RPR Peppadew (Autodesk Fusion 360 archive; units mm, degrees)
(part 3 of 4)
sketch "Sketch151" plane through (3.8207, 0, 14.3278) normal (0.2577, 0, 0.9662) x axis (0.9662, 0, -0.2577)
  line L1 (61.9037, -4.2015) -> (61.9037, -2.2015)
  line L2 (59.6949, -4.2015) -> (61.9037, -4.2015)
  line L3 (59.6949, -8.2015) -> (59.6949, -4.2015)
  line L4 (65.3871, -8.2015) -> (59.6949, -8.2015)
  line L5 (65.3871, -32.0015) -> (65.3871, -8.2015)
  line L6 (59.6949, -32.0015) -> (65.3871, -32.0015)
  line L7 (59.6949, -38.0015) -> (59.6949, -32.0015)
  line L8 (65.3871, -38.0015) -> (59.6949, -38.0015)
  line L9 (65.3871, -65.6015) -> (65.3871, -38.0015)
  line L10 (59.6949, -65.6015) -> (65.3871, -65.6015)
  line L11 (59.6949, -71.6015) -> (59.6949, -65.6015)
  line L12 (65.3871, -71.6015) -> (59.6949, -71.6015)
  line L13 (65.3871, -95.4015) -> (65.3871, -71.6015)
  line L14 (59.6949, -95.4015) -> (65.3871, -95.4015)
  line L15 (59.6949, -99.4015) -> (59.6949, -95.4015)
  line L16 (21.6089, -99.4015) -> (59.6949, -99.4015)
  line L17 (21.6089, -95.4015) -> (21.6089, -99.4015)
  line L18 (15.3992, -95.4015) -> (21.6089, -95.4015)
  line L19 (15.3992, -90.8015) -> (15.3992, -95.4015)
  line L20 (2.3072, -90.8015) -> (15.3992, -90.8015)
  line L21 (2.3072, -101.4015) -> (2.3072, -90.8015)
  line L22 (67.4569, -101.4015) -> (2.3072, -101.4015)
  line L23 (67.4569, -2.2015) -> (67.4569, -101.4015)
  line L24 (61.9037, -2.2015) -> (67.4569, -2.2015)
  line L25 (-10.2157, -101.4015) -> (-18.133, -101.4015)
  line L26 (-10.2157, -90.8015) -> (-10.2157, -101.4015)
  line L27 (-13.2688, -90.8015) -> (-10.2157, -90.8015)
  line L28 (-18.133, -90.8015) -> (-13.2688, -90.8015)
  line L29 (-18.133, -101.4015) -> (-18.133, -90.8015)
  line L30 (107.867, -38.0015) -> (10.7417, -38.0015)
  line L31 (107.867, -2.2015) -> (107.867, -38.0015)
  line L32 (-18.133, -2.2015) -> (107.867, -2.2015)
  line L33 (-18.133, -33.0015) -> (-18.133, -2.2015)
  line L34 (10.7417, -33.0015) -> (-18.133, -33.0015)
  line L35 (10.7417, -38.0015) -> (10.7417, -33.0015)
  line L36 (107.867, -133.2165) -> (107.867, -38.0015)
  line L37 (107.867, -101.4015) -> (-18.133, -101.4015)
  line L38 (107.867, -90.8015) -> (107.867, -101.4015)
  line L39 (-18.133, -90.8015) -> (107.867, -90.8015)
  line L40 (-18.133, -101.4015) -> (-18.133, -90.8015)
  line L41 (15.3992, -65.6015) -> (107.867, -65.6015)
  line L42 (15.3992, -90.8015) -> (15.3992, -65.6015)
  line L43 (107.867, -90.8015) -> (15.3992, -90.8015)
  line L44 (107.867, -65.6015) -> (107.867, -90.8015)
  line L45 (21.6089, -73.6015) -> (21.6089, -83.6015)
  line L46 (15.3992, -73.6015) -> (21.6089, -73.6015)
  circle C1 centre (64.536, -35.0015) radius 1.25
  circle C2 centre (64.4569, -5.2015) radius 1.25
  circle C3 centre (13.7417, -35.0015) radius 1.6
  circle C4 centre (-14.633, -29.5015) radius 1.6
  circle C5 centre (64.536, -35.0015) radius 1.6
  circle C6 centre (-14.633, -5.7015) radius 1.6
  circle C7 centre (64.4569, -5.2015) radius 1.6
  circle C8 centre (64.4569, -68.6015) radius 3
  circle C9 centre (64.4569, -68.6015) radius 1.25
  circle C10 centre (64.4569, -68.6015) radius 1.6
  circle C11 centre (64.4569, -98.4015) radius 3
  circle C12 centre (64.4569, -98.4015) radius 1.6
  circle C13 centre (64.4569, -98.4015) radius 1.25
  circle C14 centre (-15.133, -96.1015) radius 3
  circle C15 centre (-15.133, -96.1015) radius 1.6
  circle C16 centre (-15.133, -96.1015) radius 1.25
  circle C17 centre (18.6089, -76.6015) radius 1.6
  circle C18 centre (18.6089, -76.6015) radius 3
  circle C19 centre (18.6089, -76.6015) radius 1.25
  point P39 (107.867, -38.0015)
  point P44 (107.867, -38.0015)
  point P48 (107.867, -90.8015)
  point P28 (-18.133, -101.4015)
  point P46 (-18.133, -101.4015)
  point P23 (15.3992, -90.8015)
  point P52 (15.3992, -90.8015)
  point P50 (107.867, -65.6015)
  point P13 (65.3871, -65.6015)
  point P61 (-15.133, -96.1015)
  coincident P39 P44
  perpendicular L30 L36
  horizontal L37
  vertical L38
  horizontal L39
  vertical L40
  coincident L36 P48
  coincident P28 P46
  horizontal L41
  vertical L42
  horizontal L43
  vertical L44
  coincident P23 P52
  coincident L36 P50
  coincident P13 L41
  concentric C8 C9
  concentric C9 C10
  concentric C11 C12
  concentric C11 C13
  concentric C14 C15
  concentric C14 C16
  concentric C17 C18
  concentric C17 C19
  tangent C18 L45
  tangent C18 L46
  tangent L40 C14
  tangent L37 C11
  tangent L23 C11
  tangent L23 C8
  tangent L41 C8
  dimension "d856" diameter C8 = 6
  dimension "d857" diameter C9 = 2.5
  dimension "d858" diameter C10 = 3.2
  dimension "d859" diameter C11 = 6
  dimension "d860" diameter C12 = 3.2
  dimension "d861" diameter C13 = 2.5
  dimension "d862" diameter C14 = 6
  dimension "d863" diameter C15 = 3.2
  dimension "d864" diameter C16 = 2.5
  dimension "d865" diameter C17 = 3.2
  dimension "d866" diameter C18 = 6
  dimension "d867" diameter C19 = 2.5
  dimension "d868" distance L37 P61 = 5.3
extrude "Extrude16" cut sketch "Sketch151" profile of C9 C13 C16 C19 against normal blind 10
extrude "Extrude17" new body sketch "Sketch151" profile of L10 L11 L12 L13 L14 L15 L16 L17 L18 L19 L20 L21 L22 L23 L25 L26 L27 L28 L29 L36 L37 L38 L39 L40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 along normal blind 1
extrude "Extrude182" add of existing geometry blind 8.971
extrude "Extrude183" add of existing geometry blind 24
sketch "Sketch152" plane through (0, -33.0015, 0) normal (0, 1, 0) x axis (-1, 0, 0)
  line L1 (-9, -11) -> (-13.1998, -11)
  line L2 (-9, -2.3714) -> (-9, -11)
  line L3 (-6.9285, -2.3714) -> (-9, -2.3714)
  line L4 (-5.6202, -2.3714) -> (-6.9285, -2.3714)
  line L5 (3, -5.1) -> (-3, -5.1)
  line L6 (6.9285, -2.3714) -> (5.6202, -2.3714)
  line L7 (9, -2.3714) -> (6.9285, -2.3714)
  line L8 (9, 17.7467) -> (9, -2.3714)
  line L9 (13.7, 19) -> (9, 17.7467)
  line L10 (-6.7, 19) -> (13.7, 19)
  line L11 (-20.1998, 9.9601) -> (-14.1998, 11.5601)
  line L12 (-20.1998, 6.9601) -> (-20.1998, 9.9601)
  line L13 (-14.2, -5.0004) -> (-20.1998, 6.9601)
  line L14 (-14.2, -9.9998) -> (-14.2, -5.0004)
  line L15 (-13.1998, -11) -> (-14.2, -9.9998)
  line L16 (13.7, 19) -> (-20.1998, 9.9601)
  line L17 (14.7307, 15.1351) -> (-19.6955, 5.9548)
  line L18 (-13.1691, 7.6951) -> (-14.1998, 11.5601)
  line L19 (9, 7.6876) -> (-13.1691, 7.6951)
  line L20 (-9, -2.3714) -> (-13.1691, 7.6951)
  arc A1 centre (0, 0) radius 6.1 clockwise from (-3.66, -4.88) to (-5.6202, -2.3714)
  arc A2 centre (-3, -4) radius 1.1 clockwise from (-3, -5.1) to (-3.66, -4.88)
  arc A3 centre (3, -4) radius 1.1 clockwise from (3.66, -4.88) to (3, -5.1)
  arc A4 centre (0, 0) radius 6.1 clockwise from (5.6202, -2.3714) to (3.66, -4.88)
  arc A5 centre (-6.7, 11.5) radius 7.5 clockwise from (-14.1998, 11.5601) to (-6.7, 19)
  circle C1 centre (-7.95, 12.8) radius 1.25
  point P22 (-20.1998, 9.9601)
  point P27 (-20.1998, 9.9601)
  point P18 (13.7, 19)
  point P28 (13.7, 19)
  point P30 (-19.6955, 5.9548)
  point P20 (-14.1998, 11.5601)
  point P31 (-14.1998, 11.5601)
  point P32 (-13.1691, 7.6951)
  point P33 (9, 7.6876)
  point P4 (-9, -2.3714)
  point P34 (-9, -2.3714)
  coincident P22 P27
  coincident P18 P28
  coincident L13 P30
  coincident P20 P31
  coincident L17 P32
  perpendicular L17 L18
  midpoint L8 P33
  coincident P4 P34
extrude "Extrude184" cut sketch "Sketch152" profile of L3 L4 A1 A2 L5 A3 A4 L6 L7 L8 L19 L20 against normal blind 15
fillet "Fillet13" radius 6.5
sketch "Sketch153" plane through (0, -39.8015, 0) normal (0, -1, 0) x axis (1, 0, 0)
  line L1 (-9, -2.3714) -> (-6.9285, -2.3714)
  line L2 (-9, -6.8716) -> (-9, -2.3714)
  line L3 (-4.8712, -11.0004) -> (-9, -6.8716)
  line L4 (9, -11.0004) -> (-4.8712, -11.0004)
  line L5 (9, -11) -> (9, -11.0004)
  line L6 (14.2, -11) -> (9, -11)
  line L7 (14.2, 11.5) -> (14.2, -11)
  line L8 (-13.7, 19) -> (6.7, 19)
  line L9 (-15.7, 11) -> (-13.7, 19)
  line L10 (-15.15, 6.6) -> (-15.7, 11)
  line L11 (-9, 6.6) -> (-15.15, 6.6)
  line L12 (-9, 7.6876) -> (-9, 6.6)
  line L13 (3.4381, 7.6918) -> (-9, 7.6876)
  line L14 (9, -2.3714) -> (9.4457, -1.2953)
  line L15 (6.9285, -2.3714) -> (9, -2.3714)
  line L16 (5.6202, -2.3714) -> (6.9285, -2.3714)
  line L17 (-3, -5.1) -> (3, -5.1)
  line L18 (-6.9285, -2.3714) -> (-5.6202, -2.3714)
  line L19 (9, -11) -> (9, -2.3714)
  arc A1 centre (6.7, 11.5) radius 7.5 clockwise from (6.7, 19) to (14.2, 11.5)
  arc A2 centre (3.4403, 1.1918) radius 6.5 clockwise from (3.4381, 7.6918) to (9.4457, -1.2953)
  arc A3 centre (0, 0) radius 6.1 clockwise from (5.6202, -2.3714) to (3.66, -4.88)
  arc A4 centre (3, -4) radius 1.1 clockwise from (3.66, -4.88) to (3, -5.1)
  arc A5 centre (-3, -4) radius 1.1 clockwise from (-3, -5.1) to (-3.66, -4.88)
  arc A6 centre (0, 0) radius 6.1 clockwise from (-3.66, -4.88) to (-5.6202, -2.3714)
  circle C1 centre (7.95, 12.8) radius 1.25
  point P20 (9, -2.3714)
  point P32 (9, -2.3714)
  point P7 (9, -11)
  point P33 (9, -11)
  coincident P20 P32
  coincident P7 P33
extrude "Extrude185" cut sketch "Sketch153" profile of L1 L2 L3 L4 L5 L15 L16 A3 A4 L17 A5 A6 L18 L19 against normal blind 4
extrude "Extrude186" cut of existing geometry blind -0.5
extrude "Extrude187" cut of existing geometry blind -0.5
extrude "Extrude188" cut of existing geometry blind -0.5
sketch "Sketch154" plane through (0, -39.8015, 0) normal (0, -1, 0) x axis (1, 0, 0)
  line L1 (9, -11) -> (9, -2.3714)
  line L2 (14.2, -11) -> (9, -11)
  line L3 (14.2, 11.5) -> (14.2, -11)
  line L4 (-13.7, 19) -> (6.7, 19)
  line L5 (-15.7, 11) -> (-13.7, 19)
  line L6 (-15.15, 6.6) -> (-15.7, 11)
  line L7 (-9, 6.6) -> (-15.15, 6.6)
  line L8 (-9, 7.6876) -> (-9, 6.6)
  line L9 (3.4381, 7.6918) -> (-9, 7.6876)
  line L10 (9, -2.3714) -> (9.4457, -1.2953)
  line L11 (30, 6.8) -> (7.95, 6.8)
  line L12 (101, -13.4655) -> (108.0456, -13.4655)
  line L13 (69.0228, -2.6624) -> (101, -13.4655)
  line L14 (30, 6.8) -> (69.0228, -2.6624)
  line L15 (72, -1) -> (108.0456, -13.4655)
  line L16 (9.7456, 18.525) -> (72, -1)
  arc A1 centre (6.7, 11.5) radius 7.5 clockwise from (6.7, 19) to (14.2, 11.5)
  arc A2 centre (3.4403, 1.1918) radius 6.5 clockwise from (3.4381, 7.6918) to (9.4457, -1.2953)
  circle C1 centre (7.95, 12.8) radius 1.25
  circle C2 centre (7.95, 12.8) radius 3.25
  circle C3 centre (7.95, 12.8) radius 6
  point P20 (7.95, 6.8)
  point P19 (108.0456, -13.4655)
  point P22 (108.0456, -13.4655)
  point P25 (108.0456, -13.4655)
  point P27 (9.7456, 18.525)
  concentric C1 C2
  concentric C2 C3
  coincident C3 P20
  tangent C3 L11
  horizontal L11
  coincident P19 P22
  horizontal L12
  coincident P19 P25
  coincident C3 P27
  tangent C3 L16
  dimension "d892" diameter C2 = 6.5
  dimension "d893" diameter C3 = 12
extrude "Extrude1" new body sketch "Sketch154" profile of L3 A1 A2 C2 C3 L11 L12 L13 L14 L15 L16 along normal blind 24
as_built_joint "As-built9" OffsetX 0 OffsetY 0 OffsetZ 0 AngleZ 0 RotateMinimum -90 RotateMaximum 0
as_built_joint "As-built10"
copy_paste "CopyPaste1"
as_built_joint "As-built11" OffsetX 0 OffsetY 0 OffsetZ 0 AngleZ 0 RotateMinimum -90 RotateMaximum 0
sketch "Sketch156" plane through (0, -63.8015, 0) normal (0, -1, 0) x axis (1, 0, 0)
  line L1 (72, -1) -> (108.0456, -13.4655)
  line L2 (9.7456, 18.525) -> (72, -1)
  line L3 (30, 6.8) -> (7.95, 6.8)
  line L4 (69.0228, -2.6624) -> (30, 6.8)
  line L5 (101, -13.4655) -> (69.0228, -2.6624)
  line L6 (108.0456, -13.4655) -> (101, -13.4655)
  line L7 (69.0228, -2.6624) -> (72, -1)
  circle C1 centre (7.95, 12.8) radius 3.25
  arc A1 centre (7.95, 12.8) radius 6 clockwise from (9.7456, 18.525) to (13.8933, 13.6228)
  arc A2 centre (6.7, 11.5) radius 7.5 clockwise from (8.5392, 18.771) to (13.8933, 13.6228)
  arc A3 centre (7.95, 12.8) radius 6 clockwise from (5.2837, 7.425) to (8.5392, 18.771)
  arc A4 centre (3.4403, 1.1918) radius 6.5 clockwise from (5.2837, 7.425) to (6.2883, 7.0347)
  arc A5 centre (7.95, 12.8) radius 6 clockwise from (7.95, 6.8) to (6.2883, 7.0347)
  point P4 (72, -1)
  point P16 (72, -1)
  point P14 (69.0228, -2.6624)
  point P17 (69.0228, -2.6624)
  coincident P4 P16
  coincident P14 P17
extrude "Extrude2" cut sketch "Sketch156" profile of L1 L5 L6 L7 against normal blind 24
sketch "Sketch157" plane through (0, -63.8015, 0) normal (0, -1, 0) x axis (1, 0, 0)
  line L1 (72, -1) -> (69.0228, -2.6624)
  line L2 (9.7456, 18.525) -> (72, -1)
  line L3 (30, 6.8) -> (7.95, 6.8)
  line L4 (69.0228, -2.6624) -> (30, 6.8)
  line L5 (9.4463, 17.5709) -> (71.7007, -1.9542)
  line L6 (33.8451, 10.9666) -> (33.5458, 10.0125)
  arc A1 centre (7.95, 12.8) radius 6 clockwise from (9.7456, 18.525) to (13.8933, 13.6228)
  arc A2 centre (6.7, 11.5) radius 7.5 clockwise from (8.5392, 18.771) to (13.8933, 13.6228)
  arc A3 centre (7.95, 12.8) radius 6 clockwise from (5.2837, 7.425) to (8.5392, 18.771)
  arc A4 centre (3.4403, 1.1918) radius 6.5 clockwise from (5.2837, 7.425) to (6.2883, 7.0347)
  arc A5 centre (7.95, 12.8) radius 6 clockwise from (7.95, 6.8) to (6.2883, 7.0347)
  circle C1 centre (7.95, 12.8) radius 3.25
  point P16 (33.5458, 10.0125)
  point P17 (33.8451, 10.9666)
  point P3 (72, -1)
  coincident L5 P16
  coincident L2 P17
  perpendicular L2 L6
  dimension "d913" = -1
  dimension "d914" distance P3 P16 = 40
extrude "Extrude3" cut sketch "Sketch157" profile of L1 L2 L5 L6 against normal blind 24
sketch "Sketch158" plane through (5.8632, 0, 18.6946) normal (0.2993, 0, 0.9542) x axis (0.9542, 0, -0.2993)
  line L1 (68.0537, -63.8015) -> (29.0121, -63.8015)
  line L2 (68.0537, -39.8015) -> (68.0537, -63.8015)
  line L3 (29.0121, -39.8015) -> (68.0537, -39.8015)
  line L4 (29.0121, -63.8015) -> (29.0121, -39.8015)
  line L5 (30.5121, -43.8015) -> (55.5121, -43.8015)
  line L6 (30.5121, -59.8015) -> (30.5121, -43.8015)
  line L7 (55.5121, -59.8015) -> (30.5121, -59.8015)
  line L8 (55.5121, -43.8015) -> (55.5121, -59.8015)
  line L9 (30.5121, -59.8015) -> (55.5121, -43.8015)
  line L10 (55.5121, -59.8015) -> (30.5121, -43.8015)
  circle C1 centre (55.5121, -43.8015) radius 1.25
  circle C2 centre (55.5121, -59.8015) radius 1.25
  circle C3 centre (30.5121, -59.8015) radius 1.25
  circle C4 centre (30.5121, -43.8015) radius 1.25
  point P10 (43.0121, -51.8015)
  point P6 (55.5121, -43.8015)
  point P11 (55.5121, -43.8015)
  point P9 (55.5121, -59.8015)
  point P12 (55.5121, -59.8015)
  point P8 (30.5121, -59.8015)
  point P13 (30.5121, -59.8015)
  point P7 (30.5121, -43.8015)
  point P14 (30.5121, -43.8015)
  horizontal L5
  perpendicular L5 L6
  parallel L5 L7
  parallel L6 L8
  coincident L9 P10
  coincident L10 P10
  coincident P6 P11
  coincident P9 P12
  coincident P8 P13
  coincident P7 P14
  dimension "d917" distance P8 P9 = 25
  dimension "d918" distance P7 P8 = 16
  dimension "d919" diameter C1 = 2.5
  dimension "d920" diameter C2 = 2.5
  dimension "d921" diameter C3 = 2.5
  dimension "d922" diameter C4 = 2.5
  dimension "d1050" distance L4 P10 = 14
extrude "Extrude4" cut sketch "Sketch158" profile of C1 C2 C3 C4 against normal blind 10
sketch "Sketch159" plane through (5.8632, 0, 18.6946) normal (0.2993, 0, 0.9542) x axis (0.9542, 0, -0.2993)
  line L1 (68.0537, -63.8015) -> (29.0121, -63.8015)
  line L2 (68.0537, -39.8015) -> (68.0537, -63.8015)
  line L3 (29.0121, -39.8015) -> (68.0537, -39.8015)
  line L4 (29.0121, -63.8015) -> (29.0121, -39.8015)
  line L5 (109.0121, -39.8015) -> (29.0121, -39.8015)
  line L6 (109.0121, -63.8015) -> (109.0121, -39.8015)
  line L7 (29.0121, -63.8015) -> (109.0121, -63.8015)
  line L8 (29.0121, -39.8015) -> (29.0121, -63.8015)
  line L9 (24.0121, -39.8015) -> (29.0121, -39.8015)
  line L10 (24.0121, -63.8015) -> (24.0121, -39.8015)
  line L11 (29.0121, -63.8015) -> (24.0121, -63.8015)
  line L12 (29.0121, -39.8015) -> (29.0121, -63.8015)
  circle C1 centre (55.5121, -43.8015) radius 1.25
  circle C2 centre (55.5121, -59.8015) radius 1.25
  circle C3 centre (30.5121, -43.8015) radius 1.25
  circle C4 centre (30.5121, -59.8015) radius 1.25
  circle C5 centre (55.5121, -59.8015) radius 1.6
  circle C6 centre (55.5121, -43.8015) radius 1.6
  circle C7 centre (30.5121, -43.8015) radius 1.6
  circle C8 centre (30.5121, -59.8015) radius 1.6
  point P9 (29.0121, -39.8015)
  point P10 (29.0121, -39.8015)
  point P3 (55.5121, -59.8015)
  point P15 (55.5121, -59.8015)
  point P11 (109.0121, -39.8015)
  point P19 (24.0121, -39.8015)
  horizontal L5
  vertical L6
  horizontal L7
  vertical L8
  coincident P9 P10
  concentric C1 C6
  concentric C3 C7
  concentric C4 C8
  coincident P3 P15
  horizontal L9
  vertical L10
  horizontal L11
  vertical L12
  dimension "d925" distance P10 P11 = 80
  dimension "d926" diameter C5 = 3.2
  dimension "d927" diameter C6 = 3.2
  dimension "d928" diameter C7 = 3.2
  dimension "d929" diameter C8 = 3.2
  dimension "d1070" distance P10 P19 = 5
extrude "Extrude1" new body sketch "Sketch159" profile of L1 L2 L3 L4 L5 L6 L7 L8 C5 C6 C7 C8 L9 L10 L11 L12 along normal blind 1
as_built_joint "As-built12"
fillet "Fillet14" radius 3.5
fillet "Fillet15" radius 3
extrude "Extrude189" cut of existing geometry blind -5
delete_face "DeleteFace5"
extrude "Extrude190" cut of existing geometry blind -4
sketch "Sketch161" plane through (0, 0, -11.5) normal (0, 0, 1) x axis (1, 0, 0)
  line L1 (18.7, -99.4015) -> (18.7, -73.6015)
  line L2 (61.5, -99.4015) -> (18.7, -99.4015)
  line L3 (61.5, -98.4015) -> (61.5, -99.4015)
  line L4 (67, -95.4015) -> (64.5, -95.4015)
  line L5 (67, -71.8015) -> (67, -95.4015)
  line L6 (19, -71.8015) -> (67, -71.8015)
  line L7 (19, -73.601) -> (19, -71.8015)
  line L8 (9, -73.601) -> (19, -73.601)
  line L9 (9, -73.6015) -> (9, -73.601)
  line L10 (18.7, -73.6015) -> (9, -73.6015)
  line L11 (24.7, -76.6015) -> (24.7, -80.6015)
  line L12 (18.7, -73.6015) -> (21.7, -73.6015)
  line L13 (18.7, -83.6015) -> (18.7, -73.6015)
  line L14 (21.7, -83.6015) -> (18.7, -83.6015)
  arc A1 centre (64.5, -98.4015) radius 3 clockwise from (61.5, -98.4015) to (64.5, -95.4015)
  arc A2 centre (21.7, -80.6015) radius 3 clockwise from (24.7, -80.6015) to (21.7, -83.6015)
  arc A3 centre (21.7, -76.6015) radius 3 clockwise from (21.7, -73.6015) to (24.7, -76.6015)
  closed curve K1 centre (21.8013, -76.6015)
extrude "Extrude191" add sketch "Sketch161" profile of L1 A2 L11 A3 L12 L13 L14 K1 along normal blind 0.5
sketch "Sketch162" plane through (18.7, 0, 0) normal (1, 0, 0) x axis (0, 0, -1)
  line L1 (11, -73.6015) -> (11, -83.6015)
  line L2 (-19, -73.6015) -> (11, -73.6015)
  line L3 (-19, -83.6015) -> (-19, -73.6015)
  line L4 (-6.6, -83.6015) -> (-19, -83.6015)
  line L5 (-6.6, -90.8015) -> (-6.6, -83.6015)
  line L6 (-10.36, -90.8015) -> (-6.6, -90.8015)
  line L7 (-10.36, -99.4015) -> (-10.36, -90.8015)
  line L8 (11.5, -99.4015) -> (-10.36, -99.4015)
  line L9 (11.5, -83.6015) -> (11.5, -99.4015)
  line L10 (11, -83.6015) -> (11.5, -83.6015)
  line L11 (-0.0106, -77.7274) -> (-0.0106, -75.4756)
  line L12 (-9.56, -83.6015) -> (11, -83.6015)
  line L13 (-10.36, -83.6015) -> (-9.56, -83.6015)
  line L14 (11, -83.6015) -> (-10.36, -83.6015)
  closed curve K1 centre (2.0969, -76.6015)
extrude "Extrude192" cut sketch "Sketch162" profile of L5 L6 L7 L8 L9 L10 L12 L14 against normal blind 8
extrude "Extrude193" cut of existing geometry blind -5
extrude "Extrude194" cut of existing geometry blind -4
sketch "Sketch163" plane through (0, -39.8015, 0) normal (0, -1, 0) x axis (1, 0, 0)
  line L1 (9, -11) -> (9, -2.3714)
  line L2 (14.2, -11) -> (9, -11)
  line L3 (14.2, 11.5) -> (14.2, -11)
  line L4 (-13.7, 19) -> (6.7, 19)
  line L5 (-15.7, 11) -> (-13.7, 19)
  line L6 (-15.15, 6.6) -> (-15.7, 11)
  line L7 (-9, 6.6) -> (-15.15, 6.6)
  line L8 (-9, 7.6876) -> (-9, 6.6)
  line L9 (3.4381, 7.6918) -> (-9, 7.6876)
  line L10 (9, -2.3714) -> (9.4457, -1.2953)
  line L11 (-15.7, 11) -> (-15.15, 6.6)
  line L12 (-13.7, -5) -> (-15.7, 11)
  line L13 (-15.7, 11) -> (-13.7, -5)
  line L14 (-15.15, 6.6) -> (-15.7, 11)
  line L15 (-13.7, -5) -> (-5.7, -13)
  line L16 (-5.7, -13) -> (-13.7, -5)
  line L17 (-13.15, 6.6) -> (-15.15, 6.6)
  line L18 (-11.8006, -4.071) -> (-4.2858, -11.5858)
  line L19 (-13.7154, 11.2481) -> (-11.8006, -4.071)
  line L20 (-4.9315, -13) -> (-4.2858, -11.5858)
  line L21 (-3.5947, 6.6) -> (-13.15, 6.6)
  line L22 (-4.2858, -11.5858) -> (-3.5947, 6.6)
  line L23 (65.5, -13) -> (69, -13)
  line L24 (-5.7, -13) -> (65.5, -13)
  line L25 (65.5, -13) -> (-5.7, -13)
  line L26 (65.5, -13) -> (69, -13)
  line L27 (4.4315, -13) -> (-4.4315, -13)
  line L28 (-4.4315, -13) -> (4.4315, -13)
  line L29 (4.4315, -13) -> (-4.4315, -13)
  line L30 (-4.4315, -13) -> (4.4315, -13)
  line L31 (-4.4315, -13) -> (4.4315, -13)
  line L32 (4.4315, -13) -> (-4.4315, -13)
  line L33 (-4.4315, -13) -> (4.4315, -13)
  line L34 (4.4315, -13) -> (-4.4315, -13)
  line L35 (20.7268, -13) -> (29.6727, -13)
  line L36 (29.6727, -13) -> (20.7268, -13)
  line L37 (20.7268, -13) -> (29.6727, -13)
  line L38 (29.6727, -13) -> (20.7268, -13)
  line L39 (63.6085, -13) -> (64.5364, -13)
  arc A1 centre (6.7, 11.5) radius 7.5 clockwise from (6.7, 19) to (14.2, 11.5)
  arc A2 centre (3.4403, 1.1918) radius 6.5 clockwise from (3.4381, 7.6918) to (9.4457, -1.2953)
  circle C1 centre (7.95, 12.8) radius 1.25
  point P17 (-15.15, 6.6)
  point P22 (-15.15, 6.6)
  point P23 (-13.15, 6.6)
  coincident P17 P22
  coincident L7 P23
  parallel L7 L17
  perpendicular L8 L21
  dimension "d952" distance P22 P23 = 2
  dimension "d953" = 2
extrude "Extrude195" cut sketch "Sketch163" profile of L7 L18 L19 L21 L22 along normal blind 33.8
sketch "Sketch164" plane through (0, -35.8015, 0) normal (0, -1, 0) x axis (1, 0, 0)
  line L1 (5.6202, -2.3714) -> (6.9285, -2.3714)
  line L2 (-3, -5.1) -> (3, -5.1)
  line L3 (-6.9285, -2.3714) -> (-5.6202, -2.3714)
  line L4 (-9, -2.3714) -> (-6.9285, -2.3714)
  line L5 (-9, -6.8716) -> (-9, -2.3714)
  line L6 (-4.8712, -11.0004) -> (-9, -6.8716)
  line L7 (9, -11.0004) -> (-4.8712, -11.0004)
  line L8 (9, -11) -> (9, -11.0004)
  line L9 (9, -2.3714) -> (9, -11)
  line L10 (6.9285, -2.3714) -> (9, -2.3714)
  line L11 (5.6202, -2.8729) -> (5.6202, -2.3714)
  line L12 (5.6202, -11.0004) -> (5.6202, -2.8729)
  arc A1 centre (0, 0) radius 6.1 clockwise from (5.6202, -2.3714) to (3.66, -4.88)
  arc A2 centre (3, -4) radius 1.1 clockwise from (3.66, -4.88) to (3, -5.1)
  arc A3 centre (-3, -4) radius 1.1 clockwise from (-3, -5.1) to (-3.66, -4.88)
  arc A4 centre (0, 0) radius 6.1 clockwise from (-3.66, -4.88) to (-5.6202, -2.3714)
  point P3 (5.6202, -2.3714)
  point P19 (5.6202, -2.3714)
  point P21 (5.6202, -11.0004)
  coincident P3 P19
  perpendicular L1 L11
  coincident L7 P21
  perpendicular L7 L12
extrude "Extrude196" cut sketch "Sketch164" profile of A1 A2 L2 A3 A4 L3 L4 L5 L6 L7 L11 L12 against normal blind 6.7
sketch "Sketch165" plane through (0, -39.8015, 0) normal (0, -1, 0) x axis (1, 0, 0)
  line L1 (9, -11) -> (9, -2.3714)
  line L2 (14.2, -11) -> (9, -11)
  line L3 (14.2, 11.5) -> (14.2, -11)
  line L4 (-13.7, 19) -> (6.7, 19)
  line L5 (-15.7, 11) -> (-13.7, 19)
  line L6 (-15.15, 6.6) -> (-15.7, 11)
  line L7 (-13.1344, 6.6) -> (-15.15, 6.6)
  line L8 (-11.8006, -4.071) -> (-13.1344, 6.6)
  line L9 (-9, -6.8716) -> (-11.8006, -4.071)
  line L10 (-9, -2.3714) -> (-9, -6.8716)
  line L11 (-9, 6.6) -> (-9, -2.3714)
  line L12 (-9, 7.6876) -> (-9, 6.6)
  line L13 (3.4381, 7.6918) -> (-9, 7.6876)
  line L14 (9, -2.3714) -> (9.4457, -1.2953)
  line L15 (-13.1344, 7.6876) -> (-9, 7.6876)
  line L16 (-13.1344, 6.6) -> (-13.1344, 7.6876)
  arc A1 centre (6.7, 11.5) radius 7.5 clockwise from (6.7, 19) to (14.2, 11.5)
  arc A2 centre (3.4403, 1.1918) radius 6.5 clockwise from (3.4381, 7.6918) to (9.4457, -1.2953)
  circle C1 centre (7.95, 12.8) radius 1.25
  point P16 (-9, 7.6876)
  point P21 (-9, 7.6876)
  point P11 (-13.1344, 6.6)
  point P23 (-13.1344, 6.6)
  coincident P16 P21
  perpendicular L12 L15
  coincident P11 P23
  perpendicular L7 L16
extrude "Extrude197" cut sketch "Sketch165" profile of L8 L9 L10 L11 L12 L15 L16 against normal blind 10.7
sketch "Sketch166" plane through (0, -29.1015, 0) normal (0, -1, 0) x axis (1, 0, 0)
  line L1 (-3, -5.1) -> (3, -5.1)
  line L2 (-6.9285, -2.3714) -> (-5.6202, -2.3714)
  line L3 (-9, -2.3714) -> (-6.9285, -2.3714)
  line L4 (-9, 7.6876) -> (-9, -2.3714)
  line L5 (-11.8687, 7.6876) -> (-9, 7.6876)
  line L6 (-11.8006, -4.071) -> (-13.1344, 6.6)
  line L7 (-4.8712, -11.0004) -> (-11.8006, -4.071)
  line L8 (5.6202, -11.0004) -> (-4.8712, -11.0004)
  line L9 (5.6202, -2.8729) -> (5.6202, -11.0004)
  line L10 (5.6202, -2.3714) -> (5.6202, -2.8729)
  line L11 (-11.9667, -2.7422) -> (-9, -2.3714)
  line L12 (-12.0082, 7.1645) -> (-11.8687, 7.6876)
  line L13 (-13.1344, 7.4648) -> (-12.0082, 7.1645)
  line L14 (-13.1344, 6.6) -> (-13.1344, 7.4648)
  arc A1 centre (-3, -4) radius 1.1 clockwise from (-3, -5.1) to (-3.66, -4.88)
  arc A2 centre (0, 0) radius 6.1 clockwise from (-3.66, -4.88) to (-5.6202, -2.3714)
  arc A3 centre (0, 0) radius 6.1 clockwise from (5.6202, -2.3714) to (3.66, -4.88)
  arc A4 centre (3, -4) radius 1.1 clockwise from (3.66, -4.88) to (3, -5.1)
  point P9 (-9, -2.3714)
  point P20 (-9, -2.3714)
  point P21 (-11.9667, -2.7422)
  coincident P9 P20
  coincident L6 P21
  perpendicular L6 L11
extrude "Extrude198" cut sketch "Sketch166" profile of L4 L5 L6 L11 against normal blind 16.3
chamfer "Chamfer13" distance 4
chamfer "Chamfer14" distance 2
sketch "Sketch167" plane through (0, 0, -11.5004) normal (0, 0, 1) x axis (1, 0, 0)
  line L1 (22.4159, -28.7015) -> (27.9836, -28.7015)
  line L2 (22.4159, -38.0015) -> (22.4159, -28.7015)
  line L3 (13.1998, -38.0015) -> (22.4159, -38.0015)
  line L4 (13.1998, -8.2015) -> (13.1998, -38.0015)
  line L5 (9, -8.2015) -> (13.1998, -8.2015)
  line L6 (9, -39.8015) -> (9, -8.2015)
  line L7 (9, -71.8015) -> (9, -39.8015)
  line L8 (19, -71.8015) -> (9, -71.8015)
  line L9 (67, -71.8015) -> (19, -71.8015)
  line L10 (67, -71.6015) -> (67, -71.8015)
  line L11 (64.5, -71.6015) -> (67, -71.6015)
  line L12 (67, -65.6015) -> (64.5, -65.6015)
  line L13 (67, -38.0015) -> (67, -65.6015)
  line L14 (64.5, -38.0015) -> (67, -38.0015)
  line L15 (67, -32.0015) -> (64.5, -32.0015)
  line L16 (67, -8.2015) -> (67, -32.0015)
  line L17 (64.5, -8.2015) -> (67, -8.2015)
  line L18 (37.1998, -6.2015) -> (61.6716, -6.2015)
  line L19 (37.1998, -18.2015) -> (37.1998, -6.2015)
  line L20 (61.5, -18.2015) -> (37.1998, -18.2015)
  line L21 (61.5, -22.2015) -> (61.5, -18.2015)
  line L22 (37.1998, -22.2015) -> (61.5, -22.2015)
  line L23 (37.1998, -38.0015) -> (37.1998, -22.2015)
  line L24 (27.9836, -38.0015) -> (37.1998, -38.0015)
  line L25 (27.9836, -28.7015) -> (27.9836, -38.0015)
  line L26 (28, -38.0015) -> (22.4159, -38.0015)
  line L27 (28, -4) -> (28, -38.0015)
  line L28 (22.4159, -4) -> (28, -4)
  line L29 (22.4159, -38.0015) -> (22.4159, -4)
  arc A1 centre (64.5, -68.6015) radius 3 clockwise from (64.5, -71.6015) to (64.5, -65.6015)
  arc A2 centre (64.5, -35.0015) radius 3 clockwise from (64.5, -38.0015) to (64.5, -32.0015)
  arc A3 centre (64.5, -5.2015) radius 3 clockwise from (64.5, -8.2015) to (61.6716, -6.2015)
  point P4 (22.4159, -38.0015)
  point P33 (22.4159, -38.0015)
  horizontal L26
  vertical L27
  horizontal L28
  vertical L29
  coincident P4 P33
extrude "Extrude199" add sketch "Sketch167" profile of L1 L2 L24 L25 L26 L27 L28 L29 along normal blind 0.5
extrude "Extrude200" add of existing geometry blind 0.5
sketch "Sketch168" plane through (0, -4.2015, 0) normal (0, -1, 0) x axis (1, 0, 0)
  line L1 (22.4159, -10.5004) -> (22.4159, -11.0004)
  line L2 (27.9836, -10.5004) -> (22.4159, -10.5004)
  line L3 (27.9836, -11.0004) -> (27.9836, -10.5004)
  line L4 (35.1998, -9) -> (31.0096, -9)
  line L5 (36.3091, 0.4895) -> (35.1998, -9)
  line L6 (52.8737, -3.9277) -> (36.3091, 0.4895)
  line L7 (9, 12.9467) -> (51.698, 1.5605)
  line L8 (9, -11) -> (9, 12.9467)
  line L9 (13.1998, -11) -> (9, -11)
  line L10 (15.1998, -9) -> (13.1998, -11)
  line L11 (19.3899, -9) -> (15.1998, -9)
  line L12 (35.1998, -9) -> (15.1998, -9)
  arc A1 centre (25.1998, -3.5004) radius 8 clockwise from (31.0096, -9) to (27.9836, -11.0004)
  arc A2 centre (57.6661, -0.031) radius 6.1767 clockwise from (52.8737, -3.9277) to (51.698, 1.5605)
  arc A3 centre (25.1998, -3.5004) radius 8 clockwise from (22.4159, -11.0004) to (19.3899, -9)
  circle C1 centre (25.1998, -2.5004) radius 8
  circle C2 centre (25.1998, -2.5004) radius 8.9443
  point P5 (27.9836, -11.0004)
  point P16 (15.1998, -9)
  point P20 (15.1998, -9)
  point P8 (35.1998, -9)
  point P21 (35.1998, -9)
  point P18 (25.1998, -2.5004)
  concentric C1 C2
  coincident P5 C2
  coincident P16 P20
  coincident P8 P21
  dimension "d970" diameter C1 = 16
  dimension "d971" distance L2 P18 = 8
extrude "Extrude201" add sketch "Sketch168" profile of L1 L2 L3 A1 A3 C1 L12 along normal blind 33.8
combine "Combine3"
sketch "Sketch171" plane through (0, 0, 19) normal (0, 0, 1) x axis (1, 0, 0)
  line L1 (18.7, -73.6015) -> (18.7, -83.6015)
  line L2 (14.2, -73.6015) -> (18.7, -73.6015)
  line L3 (14.2, -83.6015) -> (14.2, -73.6015)
  line L4 (18.7, -83.6015) -> (14.2, -83.6015)
  line L5 (24.7, -76.6015) -> (24.7, -80.6015)
  line L6 (18.7, -73.6015) -> (21.7, -73.6015)
  line L7 (18.7, -83.6015) -> (18.7, -73.6015)
  line L8 (21.7, -83.6015) -> (18.7, -83.6015)
  arc A1 centre (21.7, -80.6015) radius 3 clockwise from (24.7, -80.6015) to (21.7, -83.6015)
  arc A2 centre (21.7, -76.6015) radius 3 clockwise from (21.7, -73.6015) to (24.7, -76.6015)
  closed curve K1 centre (21.8013, -76.6015)
sketch "Sketch172" plane through (0, -2.2015, 0) normal (0, 1, 0) x axis (-1, 0, 0)
  line L1 (13.7, -5) -> (5.7, -13)
  line L2 (15.7, 11) -> (13.7, -5)
  line L3 (13.7, 19) -> (15.7, 11)
  line L4 (6.05, 16.96) -> (13.7, 19)
  line L5 (6.05, 4.95) -> (6.05, 16.96)
  line L6 (3, 4.95) -> (6.05, 4.95)
  line L7 (3, 0) -> (3, 4.95)
  line L8 (-3, 4.95) -> (-3, 0)
  line L9 (-6.05, 4.95) -> (-3, 4.95)
  line L10 (-6.05, 13.7333) -> (-6.05, 4.95)
  line L11 (-51.698, 1.5605) -> (-6.05, 13.7333)
  line L12 (-65.5, -2.12) -> (-63.6343, -1.6225)
  line L13 (-65.5, -13) -> (-65.5, -2.12)
  line L14 (5.7, -13) -> (-65.5, -13)
  arc A1 centre (0, 0) radius 3 clockwise from (3, 0) to (-3, 0)
  arc A2 centre (-57.6661, -0.031) radius 6.1767 clockwise from (-51.698, 1.5605) to (-63.6343, -1.6225)
  circle C1 centre (-8.1677, 13.1686) radius 5.5309
  point P20 (-8.1677, 13.1686)
  coincident L11 P20
extrude "Extrude202" cut sketch "Sketch172" profile of L10 L11 C1 against normal blind 21
sketch "Sketch173" plane through (0, -2.2015, 0) normal (0, 1, 0) x axis (-1, 0, 0)
  line L1 (-51.698, 1.5605) -> (-13.5118, 11.7435)
  line L2 (-65.5, -2.12) -> (-63.6343, -1.6225)
  line L3 (-65.5, -13) -> (-65.5, -2.12)
  line L4 (5.7, -13) -> (-65.5, -13)
  line L5 (13.7, -5) -> (5.7, -13)
  line L6 (15.7, 11) -> (13.7, -5)
  line L7 (13.7, 19) -> (15.7, 11)
  line L8 (6.05, 16.96) -> (13.7, 19)
  line L9 (6.05, 4.95) -> (6.05, 16.96)
  line L10 (3, 4.95) -> (6.05, 4.95)
  line L11 (3, 0) -> (3, 4.95)
  line L12 (-3, 4.95) -> (-3, 0)
  line L13 (-6.05, 4.95) -> (-3, 4.95)
  line L14 (-6.05, 8.0592) -> (-6.05, 4.95)
  line L15 (8.7, -13) -> (13.7, -5)
  line L16 (5.7, -13) -> (8.7, -13)
  arc A1 centre (-8.1677, 13.1686) radius 5.5309 clockwise from (-6.05, 8.0592) to (-13.5118, 11.7435)
  arc A2 centre (-57.6661, -0.031) radius 6.1767 clockwise from (-51.698, 1.5605) to (-63.6343, -1.6225)
  arc A3 centre (0, 0) radius 3 clockwise from (3, 0) to (-3, 0)
  point P11 (13.7, -5)
  point P22 (13.7, -5)
  point P10 (5.7, -13)
  point P24 (5.7, -13)
  point P23 (8.7, -13)
  coincident P11 P22
  coincident P10 P24
  parallel L4 L16
  dimension "d980" distance P23 P24 = 3
extrude "Extrude203" add sketch "Sketch173" profile of L5 L15 L16 against normal blind 99.2
chamfer "Chamfer15" distance 0.5
extrude "Extrude204" add sketch "Sketch171" profile of L1 A1 L5 A2 L6 L7 L8 K1 against normal blind 22
chamfer "Chamfer16" distance 7
sketch "Sketch174" plane through (4.0784, 0, 15.294) normal (0.2577, 0, 0.9662) x axis (0.9662, 0, -0.2577)
  line L1 (107.867, -65.6015) -> (107.867, -101.4015)
  line L2 (15.3992, -65.6015) -> (107.867, -65.6015)
  line L3 (15.3992, -90.8015) -> (15.3992, -65.6015)
  line L4 (-18.133, -90.8015) -> (15.3992, -90.8015)
  line L5 (-18.133, -101.4015) -> (-18.133, -90.8015)
  line L6 (107.867, -101.4015) -> (-18.133, -101.4015)
  line L7 (21.8992, -65.6015) -> (15.3992, -65.6015)
  line L8 (21.8992, -90.8015) -> (21.8992, -65.6015)
  line L9 (15.3992, -90.8015) -> (21.8992, -90.8015)
  line L10 (15.3992, -65.6015) -> (15.3992, -90.8015)
  circle C1 centre (64.4569, -68.6015) radius 1.6
  circle C2 centre (18.6089, -76.6015) radius 1.6
  circle C3 centre (-15.133, -96.1015) radius 1.6
  circle C4 centre (64.4569, -98.4015) radius 1.6
  point P8 (15.3992, -65.6015)
  point P12 (15.3992, -65.6015)
  point P13 (21.8992, -65.6015)
  horizontal L7
  vertical L8
  horizontal L9
  vertical L10
  coincident P8 P12
  dimension "d987" distance P12 P13 = 6.5
extrude "Extrude20" cut sketch "Sketch174" profile of C2 L2 L3 L7 L8 L9 L10 against normal blind 1
chamfer "Chamfer1" distance 4.6
fillet "Fillet2" radius 5.5
delete_face "DeleteFace1"
extrude "Extrude21" cut of existing geometry blind -2
sketch "Sketch175" plane through (0, -90.8015, 0) normal (0, 1, 0) x axis (-1, 0, 0)
  line L1 (4.4315, -12.5) -> (-4.4315, -12.5)
  line L2 (4.4315, -7.2615) -> (4.4315, -12.5)
  line L3 (7.467, -2.3714) -> (6.6499, -4.414)
  line L4 (9, -2.3714) -> (7.467, -2.3714)
  line L5 (9, 17.7467) -> (9, -2.3714)
  line L6 (6.05, 16.96) -> (9, 17.7467)
  line L7 (6.05, -5.05) -> (6.05, 16.96)
  line L8 (4.5768, -5.05) -> (6.05, -5.05)
  line L9 (-0.6148, -7) -> (0.6148, -7)
  line L10 (-6.05, -5.05) -> (-4.5768, -5.05)
  line L11 (-6.05, 13.7333) -> (-6.05, -5.05)
  line L12 (-10.7, 12.4933) -> (-6.05, 13.7333)
  line L13 (-10.7, 6.6) -> (-10.7, 12.4933)
  line L14 (-9, 6.6) -> (-10.7, 6.6)
  line L15 (-9, -2.3714) -> (-9, 6.6)
  line L16 (-7.467, -2.3714) -> (-9, -2.3714)
  line L17 (-6.6499, -4.414) -> (-7.467, -2.3714)
  line L18 (-4.4315, -12.5) -> (-4.4315, -7.2615)
  line L19 (9, 6.6) -> (-10.7, 6.6)
  line L20 (9, 17.7467) -> (9, 6.6)
  line L21 (-10.7, 17.7467) -> (9, 17.7467)
  line L22 (-10.7, 6.6) -> (-10.7, 17.7467)
  arc A1 centre (0.6148, -2) radius 6.5 clockwise from (6.6499, -4.414) to (4.4315, -7.2615)
  arc A2 centre (0.6148, -2) radius 5 clockwise from (4.5768, -5.05) to (0.6148, -7)
  arc A3 centre (-0.6148, -2) radius 5 clockwise from (-0.6148, -7) to (-4.5768, -5.05)
  arc A4 centre (-0.6148, -2) radius 6.5 clockwise from (-4.4315, -7.2615) to (-6.6499, -4.414)
  point P9 (9, 17.7467)
  point P28 (9, 17.7467)
  point P20 (-10.7, 6.6)
  point P26 (-10.7, 6.6)
  horizontal L19
  vertical L20
  horizontal L21
  vertical L22
  coincident P9 P28
  coincident P20 P26
extrude "Extrude206" cut sketch "Sketch175" profile of L5 L6 L7 L11 L12 L13 L14 L19 L20 L21 L22 against normal blind 2
sketch "Sketch176" plane through (0, -63.8015, 0) normal (0, -1, 0) x axis (1, 0, 0)
  line L1 (33.8451, 10.9666) -> (33.5458, 10.0125)
  line L2 (9.7456, 18.525) -> (33.8451, 10.9666)
  line L3 (30, 6.8) -> (7.95, 6.8)
  line L4 (69.0228, -2.6624) -> (30, 6.8)
  line L5 (70.7981, -1.6711) -> (69.0228, -2.6624)
  line L6 (33.5458, 10.0125) -> (70.7981, -1.6711)
  line L7 (8.5392, 18.771) -> (9.7456, 18.525)
  arc A1 centre (7.95, 12.8) radius 6 clockwise from (9.7456, 18.525) to (13.8933, 13.6228)
  arc A2 centre (6.7, 11.5) radius 7.5 clockwise from (8.5392, 18.771) to (13.8933, 13.6228)
  arc A3 centre (7.95, 12.8) radius 6 clockwise from (5.2837, 7.425) to (8.5392, 18.771)
  arc A4 centre (3.4403, 1.1918) radius 6.5 clockwise from (5.2837, 7.425) to (6.2883, 7.0347)
  arc A5 centre (7.95, 12.8) radius 6 clockwise from (7.95, 6.8) to (6.2883, 7.0347)
  circle C1 centre (7.95, 12.8) radius 3.25
  point P4 (9.7456, 18.525)
  point P16 (9.7456, 18.525)
  point P7 (8.5392, 18.771)
  point P17 (8.5392, 18.771)
  coincident P4 P16
  coincident P7 P17
extrude "Extrude5" add sketch "Sketch176" profile of A1 A2 L7 against normal blind 24
sketch "Sketch177" plane through (0, -39.8015, 0) normal (0, 1, 0) x axis (-1, 0, 0)
  line L1 (-33.5458, 10.0125) -> (-33.8451, 10.9666)
  line L2 (-70.7981, -1.6711) -> (-33.5458, 10.0125)
  line L3 (-69.0228, -2.6624) -> (-70.7981, -1.6711)
  line L4 (-30, 6.8) -> (-69.0228, -2.6624)
  line L5 (-7.95, 6.8) -> (-30, 6.8)
  line L6 (-9.7456, 18.525) -> (-8.5392, 18.771)
  line L7 (-33.8451, 10.9666) -> (-9.7456, 18.525)
  circle C1 centre (-7.95, 12.8) radius 3.25
  arc A1 centre (-7.95, 12.8) radius 6 clockwise from (-6.2883, 7.0347) to (-7.95, 6.8)
  arc A2 centre (-3.4403, 1.1918) radius 6.5 clockwise from (-6.2883, 7.0347) to (-5.2837, 7.425)
  arc A3 centre (-7.95, 12.8) radius 6 clockwise from (-8.5392, 18.771) to (-5.2837, 7.425)
  circle C2 centre (-7.95, 12.8) radius 1.6
  concentric C1 C2
  dimension "d1001" diameter C2 = 3.2
extrude "Extrude6" add sketch "Sketch177" profile of C1 C2 against normal blind 24
sketch "Sketch178" plane through (0, -63.8015, 0) normal (0, -1, 0) x axis (1, 0, 0)
  line L1 (33.8451, 10.9666) -> (33.5458, 10.0125)
  line L2 (9.7456, 18.525) -> (33.8451, 10.9666)
  line L3 (8.5392, 18.771) -> (9.7456, 18.525)
  line L4 (30, 6.8) -> (7.95, 6.8)
  line L5 (69.0228, -2.6624) -> (30, 6.8)
  line L6 (70.7981, -1.6711) -> (69.0228, -2.6624)
  line L7 (33.5458, 10.0125) -> (70.7981, -1.6711)
  line L8 (24.3607, 10.3) -> (7.95, 12.8)
  line L9 (30.1713, 10.9618) -> (7.4991, 16.4049)
  line L10 (5.7936, 9.5365) -> (27.9997, 8.0523)
  circle C1 centre (7.95, 12.8) radius 1.6
  arc A1 centre (7.95, 12.8) radius 6 clockwise from (5.2837, 7.425) to (8.5392, 18.771)
  arc A2 centre (3.4403, 1.1918) radius 6.5 clockwise from (5.2837, 7.425) to (6.2883, 7.0347)
  arc A3 centre (7.95, 12.8) radius 6 clockwise from (7.95, 6.8) to (6.2883, 7.0347)
  circle C2 centre (7.95, 12.8) radius 3.4
  circle C3 centre (24.3607, 10.3) radius 2
  point P14 (7.95, 12.8)
  point P15 (7.95, 12.8)
  point P16 (24.3607, 10.3)
  point P17 (24.3607, 10.3)
  concentric C1 C2
  coincident P14 P15
  coincident P16 P17
  tangent C2 L10
  tangent C3 L10
  tangent C3 L9
  tangent C2 L9
  dimension "d1004" diameter C2 = 6.8
  dimension "d1005" diameter C3 = 4
  dimension "d1006" = 20
  dimension "d1007" distance L4 P17 = 3.5
extrude "Extrude7" cut sketch "Sketch178" profile of C1 C2 C3 L9 L10 against normal blind 6.5
sketch "Sketch179" plane through (0, -63.8015, 0) normal (0, -1, 0) x axis (1, 0, 0)
  line L1 (7.7233, 9.4076) -> (24.2273, 8.3045)
  line L2 (24.8275, 12.2447) -> (8.7437, 16.1061)
  line L3 (33.8451, 10.9666) -> (33.5458, 10.0125)
  line L4 (9.7456, 18.525) -> (33.8451, 10.9666)
  line L5 (8.5392, 18.771) -> (9.7456, 18.525)
  line L6 (30, 6.8) -> (7.95, 6.8)
  line L7 (69.0228, -2.6624) -> (30, 6.8)
  line L8 (70.7981, -1.6711) -> (69.0228, -2.6624)
  line L9 (33.5458, 10.0125) -> (70.7981, -1.6711)
  arc A1 centre (7.95, 12.8) radius 3.4 clockwise from (7.7233, 9.4076) to (8.7437, 16.1061)
  arc A2 centre (24.3607, 10.3) radius 2 clockwise from (24.8275, 12.2447) to (24.2273, 8.3045)
  arc A3 centre (7.95, 12.8) radius 6 clockwise from (5.2837, 7.425) to (8.5392, 18.771)
  arc A4 centre (3.4403, 1.1918) radius 6.5 clockwise from (5.2837, 7.425) to (6.2883, 7.0347)
  arc A5 centre (7.95, 12.8) radius 6 clockwise from (7.95, 6.8) to (6.2883, 7.0347)
  circle C1 centre (7.95, 12.8) radius 10
  concentric A1 C1
  dimension "d1010" diameter C1 = 20
extrude "Extrude8" cut sketch "Sketch179" profile of L1 A1 L2 L4 L5 A3 A4 A5 L6 C1 against normal blind 3
fillet "Fillet1" radius 0.5
chamfer "Chamfer2" distance 0.5
chamfer "Chamfer1" distance 0.5
position "Position5"
sketch "Sketch180" plane through (0, -63.8015, 0) normal (0, -1, 0) x axis (1, 0, 0)
  line L1 (13.95, 34.85) -> (13.95, 21.7443)
  line L2 (23.4124, 73.8728) -> (13.95, 34.85)
  line L3 (22.4211, 75.6481) -> (23.4124, 73.8728)
  line L4 (10.7375, 38.3958) -> (22.4211, 75.6481)
  line L5 (9.7834, 38.6951) -> (10.7375, 38.3958)
  line L6 (4.9016, 23.1299) -> (9.7834, 38.6951)
  line L7 (8.5053, 29.6776) -> (6.8393, 22.7381)
  line L8 (11.9696, 21.9566) -> (12.4455, 29.0773)
  line L9 (65.5, -12.5) -> (-9.0125, -12.5)
  line L10 (65.5, -2.12) -> (65.5, -12.5)
  line L11 (6.05, 13.7333) -> (65.5, -2.12)
  line L12 (6.05, 4.95) -> (6.05, 13.7333)
  line L13 (3, 4.95) -> (6.05, 4.95)
  line L14 (3, 0) -> (3, 4.95)
  line L15 (-3, 4.95) -> (-3, 0)
  line L16 (-6.05, 4.95) -> (-3, 4.95)
  line L17 (-6.05, 16.96) -> (-6.05, 4.95)
  line L18 (-13.7, 19) -> (-6.05, 16.96)
  line L19 (-15.7, 11) -> (-13.7, 19)
  line L20 (-13.7, -5) -> (-15.7, 11)
  line L21 (-9.0125, -12.5) -> (-13.7, -5)
  line L22 (-20.3155, 14.5007) -> (7.3425, 30.9125)
  line L23 (11.3424, 12.5733) -> (11.9696, 21.9566)
  line L24 (6.8393, 22.7381) -> (4.6439, 13.5937)
  line L25 (2.225, 14.5956) -> (4.9016, 23.1299)
  line L26 (1.979, 13.3892) -> (2.225, 14.5956)
  line L27 (13.95, 21.7443) -> (13.95, 12.8)
  line L28 (6.2952, 7.0327) -> (-19.8158, 11.7344)
  line L29 (-15.3244, 13.9739) -> (8.8734, 28.3325)
  line L30 (6.8269, 9.9852) -> (-15.3244, 13.9739)
  arc A1 centre (13.45, 21.7443) radius 0.5 clockwise from (13.95, 21.7443) to (13.1881, 21.3184)
  arc A2 centre (5.3787, 22.9803) radius 0.5 clockwise from (5.5012, 22.4955) to (4.9016, 23.1299)
  arc A3 centre (7.95, 12.8) radius 10 clockwise from (5.5012, 22.4955) to (6.8393, 22.7381)
  arc A4 centre (10.45, 29.2107) radius 2 clockwise from (8.5053, 29.6776) to (12.4455, 29.0773)
  arc A5 centre (7.95, 12.8) radius 10 clockwise from (11.9696, 21.9566) to (13.1881, 21.3184)
  arc A6 centre (0, 0) radius 3 clockwise from (3, 0) to (-3, 0)
  arc A7 centre (7.95, 12.8) radius 3.4 clockwise from (11.3424, 12.5733) to (4.6439, 13.5937)
  arc A8 centre (7.95, 12.8) radius 10 clockwise from (5.5012, 22.4955) to (6.8393, 22.7381)
  arc A9 centre (5.3787, 22.9803) radius 0.5 clockwise from (5.5012, 22.4955) to (4.9016, 23.1299)
  arc A10 centre (7.95, 12.8) radius 6 clockwise from (13.325, 10.1337) to (1.979, 13.3892)
  arc A11 centre (19.5582, 8.2903) radius 6.5 clockwise from (13.325, 10.1337) to (13.7153, 11.1383)
  arc A12 centre (7.95, 12.8) radius 6 clockwise from (13.95, 12.8) to (13.7153, 11.1383)
  arc A13 centre (13.45, 21.7443) radius 0.5 clockwise from (13.95, 21.7443) to (13.1881, 21.3184)
  arc A14 centre (7.95, 12.8) radius 10 clockwise from (11.9696, 21.9566) to (13.1881, 21.3184)
  arc A15 centre (-19.55, 13.2107) radius 1.5 clockwise from (-19.8158, 11.7344) to (-20.3155, 14.5007)
  point P34 (7.3425, 30.9125)
  point P52 (6.2952, 7.0327)
  point P17 (10.45, 29.2107)
  point P55 (-19.55, 13.2107)
  midpoint L6 P34
  midpoint A10 P52
  tangent L22 A15
  tangent L28 A15
  dimension "d1019" radius A15 = 1.5
  dimension "d1020" = -3
  dimension "d1034" distance P17 P55 = 16
  dimension "d1035" distance P17 P55 = 30
extrude "Extrude9" add sketch "Sketch180" profile of L6 L12 L17 L18 L19 L22 A10 L28 A15 L29 L30 against normal blind 24
sketch "Sketch182" plane through (0, -63.8015, 0) normal (0, -1, 0) x axis (1, 0, 0)
  line L1 (13.95, 34.85) -> (13.95, 21.7443)
  line L2 (23.4124, 73.8728) -> (13.95, 34.85)
  line L3 (22.4211, 75.6481) -> (23.4124, 73.8728)
  line L4 (10.7375, 38.3958) -> (22.4211, 75.6481)
  line L5 (9.7834, 38.6951) -> (10.7375, 38.3958)
  line L6 (7.3425, 30.9125) -> (9.7834, 38.6951)
  line L7 (-20.3155, 14.5007) -> (7.3425, 30.9125)
  line L8 (6.05, 7.0769) -> (-19.8158, 11.7344)
  line L9 (6.05, 7.1088) -> (6.05, 7.0769)
  line L10 (-15.3244, 13.9739) -> (2.2925, 10.8017)
  line L11 (5.9982, 26.6264) -> (-15.3244, 13.9739)
  line L12 (4.9016, 23.1299) -> (5.9982, 26.6264)
  line L13 (8.5053, 29.6776) -> (6.8393, 22.7381)
  line L14 (11.9696, 21.9566) -> (12.4455, 29.0773)
  line L15 (11.3424, 12.5733) -> (11.9696, 21.9566)
  line L16 (6.8393, 22.7381) -> (4.6439, 13.5937)
  line L17 (2.225, 14.5956) -> (4.9016, 23.1299)
  line L18 (1.979, 13.3892) -> (2.225, 14.5956)
  line L19 (13.95, 21.7443) -> (13.95, 12.8)
  line L20 (5.9982, 26.6264) -> (7.3425, 30.9125)
  arc A1 centre (13.45, 21.7443) radius 0.5 clockwise from (13.95, 21.7443) to (13.1881, 21.3184)
  arc A2 centre (-19.55, 13.2107) radius 1.5 clockwise from (-19.8158, 11.7344) to (-20.3155, 14.5007)
  arc A3 centre (7.95, 12.8) radius 6 clockwise from (6.05, 7.1088) to (2.2925, 10.8017)
  arc A4 centre (5.3787, 22.9803) radius 0.5 clockwise from (5.5012, 22.4955) to (4.9016, 23.1299)
  arc A5 centre (7.95, 12.8) radius 10 clockwise from (5.5012, 22.4955) to (6.8393, 22.7381)
  arc A6 centre (10.45, 29.2107) radius 2 clockwise from (8.5053, 29.6776) to (12.4455, 29.0773)
  arc A7 centre (7.95, 12.8) radius 10 clockwise from (11.9696, 21.9566) to (13.1881, 21.3184)
  arc A8 centre (7.95, 12.8) radius 3.4 clockwise from (11.3424, 12.5733) to (4.6439, 13.5937)
  arc A9 centre (7.95, 12.8) radius 10 clockwise from (5.5012, 22.4955) to (6.8393, 22.7381)
  arc A10 centre (5.3787, 22.9803) radius 0.5 clockwise from (5.5012, 22.4955) to (4.9016, 23.1299)
  arc A11 centre (7.95, 12.8) radius 6 clockwise from (2.2925, 10.8017) to (1.979, 13.3892)
  arc A12 centre (7.95, 12.8) radius 6 clockwise from (6.05, 7.1088) to (2.2925, 10.8017)
  arc A13 centre (7.95, 12.8) radius 6 clockwise from (13.325, 10.1337) to (6.05, 7.1088)
  arc A14 centre (19.5582, 8.2903) radius 6.5 clockwise from (13.325, 10.1337) to (13.7153, 11.1383)
  arc A15 centre (7.95, 12.8) radius 6 clockwise from (13.95, 12.8) to (13.7153, 11.1383)
  arc A16 centre (13.45, 21.7443) radius 0.5 clockwise from (13.95, 21.7443) to (13.1881, 21.3184)
  arc A17 centre (7.95, 12.8) radius 10 clockwise from (11.9696, 21.9566) to (13.1881, 21.3184)
  point P10 (7.3425, 30.9125)
  point P47 (7.3425, 30.9125)
  point P19 (5.9982, 26.6264)
  point P48 (5.9982, 26.6264)
  coincident P10 P47
  coincident P19 P48
extrude "Extrude12" cut sketch "Sketch182" profile of L7 A2 L8 L9 A3 L10 L11 A12 L20 against normal blind 20
position "Position6"
extrude "Extrude207" add of existing geometry blind 2
fillet "Fillet3" radius 1
sketch "Sketch183" plane through (0, -33.0015, 0) normal (0, 1, 0) x axis (-1, 0, 0)
  line L1 (9, 7.6876) -> (-3.4381, 7.6918)
  line L2 (13, 7.6876) -> (9, 7.6876)
  line L3 (9, 11.6876) -> (13, 7.6876)
  line L4 (9, 17.7467) -> (9, 11.6876)
  line L5 (13.7, 19) -> (9, 17.7467)
  line L6 (-6.7, 19) -> (13.7, 19)
  line L7 (-20.1998, 9.9601) -> (-14.1998, 11.5601)
  line L8 (-20.1998, 6.9601) -> (-20.1998, 9.9601)
  line L9 (-14.2, -5.0004) -> (-20.1998, 6.9601)
  line L10 (-14.2, -9.9998) -> (-14.2, -5.0004)
  line L11 (-13.1998, -11) -> (-14.2, -9.9998)
  line L12 (-9, -11) -> (-13.1998, -11)
  line L13 (-9, -2.3714) -> (-9, -11)
  line L14 (-9.4457, -1.2953) -> (-9, -2.3714)
  arc A1 centre (-6.7, 11.5) radius 7.5 clockwise from (-14.1998, 11.5601) to (-6.7, 19)
  arc A2 centre (-3.4403, 1.1918) radius 6.5 clockwise from (-9.4457, -1.2953) to (-3.4381, 7.6918)
  circle C1 centre (-7.95, 12.8) radius 1.25
sketch "Sketch184" plane through (4.0784, 0, 15.294) normal (0.2577, 0, 0.9662) x axis (0.9662, 0, -0.2577)
  line L1 (-17.633, -32.5015) -> (-17.633, -2.7015)
  line L2 (11.2417, -32.5015) -> (-17.633, -32.5015)
  line L3 (11.2417, -37.5015) -> (11.2417, -32.5015)
  line L4 (107.367, -37.5015) -> (11.2417, -37.5015)
  line L5 (107.367, -2.7015) -> (107.367, -37.5015)
  line L6 (-17.633, -2.7015) -> (107.367, -2.7015)
  line L7 (5.6335, -33.0015) -> (3.1335, -33.0015)
  line L8 (3.1335, -39.8015) -> (5.6335, -39.8015)
  line L9 (7.8835, -29.5015) -> (0.8835, -29.5015)
  line L10 (7.8835, -36.5015) -> (7.8835, -29.5015)
  line L11 (0.8835, -36.5015) -> (7.8835, -36.5015)
  line L12 (0.8835, -29.5015) -> (0.8835, -36.5015)
  line L13 (7.8835, -36.5015) -> (0.8835, -29.5015)
  line L14 (0.8835, -36.5015) -> (7.8835, -29.5015)
  circle C1 centre (64.4569, -5.2015) radius 2.1
  circle C2 centre (64.536, -35.0015) radius 2.1
  circle C3 centre (13.7417, -35.0015) radius 2.1
  circle C4 centre (-14.633, -29.5015) radius 2.1
  circle C5 centre (-14.633, -5.7015) radius 2.1
  circle C6 centre (4.3835, -33.0015) radius 3
  point P17 (4.3835, -33.0015)
  point P22 (4.3835, -33.0015)
  point P20 (7.8835, -36.5015)
  point P21 (0.8835, -36.5015)
  point P19 (7.8835, -29.5015)
  midpoint L7 P17
  horizontal L9
  perpendicular L9 L10
  parallel L9 L11
  parallel L10 L12
  coincident L13 P22
  coincident L14 P22
  coincident P17 P22
  dimension "d1038" diameter C6 = 6
  dimension "d1039" distance P20 P21 = 7
  dimension "d1040" distance P19 P20 = 7
extrude "Extrude22" cut sketch "Sketch184" profile of L2 C6 L9 L10 L11 L12 against normal blind 1
chamfer "Chamfer4" distance 0.5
